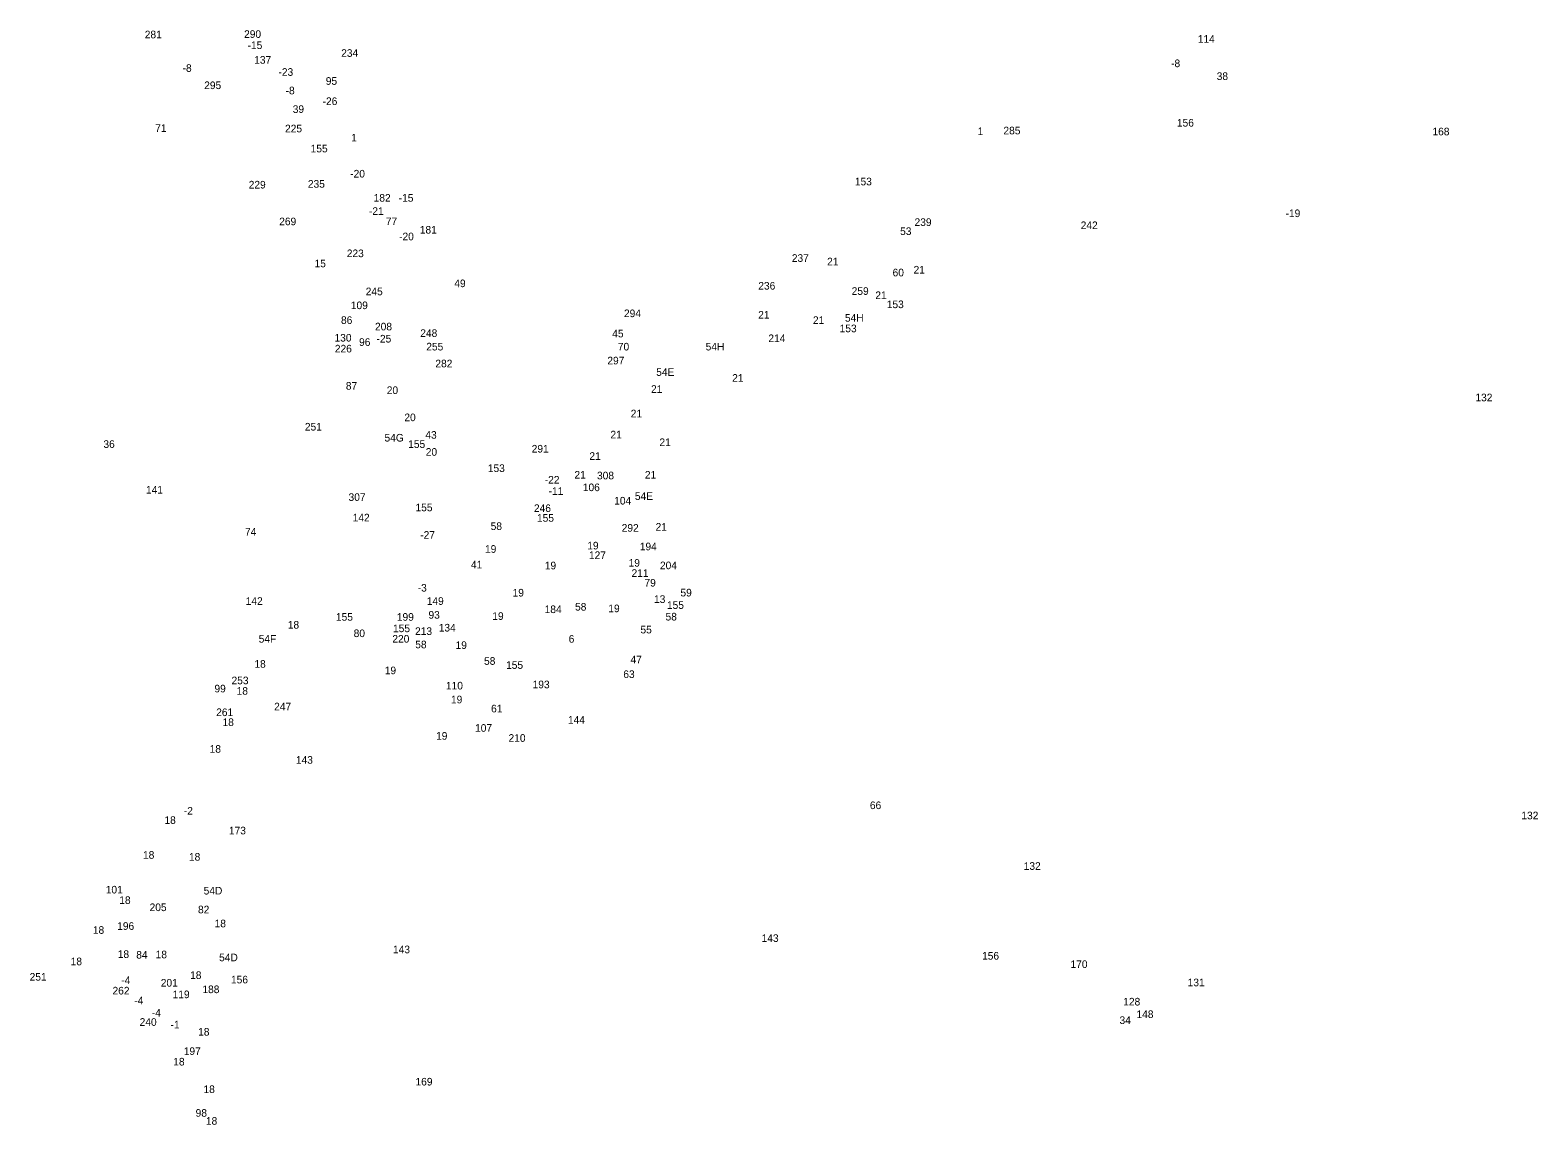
# Model space of a CAD drawing. Extents: x -784627 to -783624, y -969855 to -968411.
# Drawn here: x -784627 to -783638, y -969855 to -969137 of the extents above; entities that cross this region are included whole.
import ezdxf

# ---------------------------------------------------------------- set-up
doc = ezdxf.new("R2010")
doc.units = 0
doc.layers.add('Vrstva 15', color=7, linetype='Continuous')
doc.layers.add('Vrstva 24', color=7, linetype='Continuous')

msp = doc.modelspace()

# ---------------------------------------------------------------- texts
at = {"layer": 'Vrstva 15'}
for s, p in [('-15', (-784484.077, -969149.12)), ('-8', (-784526.71, -969164.1)), ('137', (-784479.74, -969158.75)), ('-23', (-784463.81, -969166.69)), ('-8', (-783878.23, -969160.99)), ('95', (-784432.774, -969172.57)), ('38', (-783848.323, -969169.42)), ('-8', (-784459.13, -969178.86)), ('-26', (-784434.862, -969185.85)), ('39', (-784454.465, -969191.04)), ('71', (-784544.67, -969203.48)), ('1', (-784005.14, -969205.6)), ('156', (-783874.422, -969200.01)), ('155', (-784442.7, -969216.92)), ('1', (-784416.09, -969209.79)), ('-20', (-784416.75, -969233.43)), ('153', (-784085.68, -969238.57)), ('182', (-784401.37, -969249.26)), ('-15', (-784384.947, -969249.3)), ('-21', (-784404.457, -969257.95)), ('77', (-784393.362, -969264.67)), ('-19', (-783803.139, -969259.4)), ('-20', (-784384.68, -969274.61)), ('181', (-784371.098, -969270.22)), ('53', (-784055.993, -969271.16)), ('15', (-784440.14, -969292.35)), ('21', (-784103.9, -969291.09)), ('49', (-784348.463, -969305.39)), ('60', (-784060.935, -969298.28)), ('109', (-784416.332, -969319.8)), ('153', (-784064.77, -969319.14)), ('86', (-784422.795, -969329.51)), ('153', (-784095.68, -969334.95)), ('54H', (-784092.201, -969328.03)), ('130', (-784427.04, -969341.08)), ('96', (-784410.946, -969343.92)), ('-25', (-784399.47, -969341.71)), ('45', (-784244.851, -969338.33)), ('70', (-784241.162, -969346.93)), ('54H', (-784183.571, -969346.92)), ('54E', (-784216.003, -969363.58)), ('  87', (-784423.342, -969372.67)), ('20', (-784392.774, -969375.5)), ('21', (-784219.42, -969374.74)), ('21', (-784166.18, -969367.46)), ('20', (-784381.214, -969393.33)), ('21', (-784232.73, -969390.82)), ('43', (-784367.461, -969404.84)), ('21', (-784246.04, -969404.64)), ('36', (-784578.665, -969410.86)), ('54G', (-784394.239, -969406.7)), ('155', (-784378.72, -969410.87)), ('21', (-784213.9, -969409.66)), ('20', (-784367.184, -969416.02)), ('21', (-784259.85, -969418.71)), ('153', (-784326.49, -969426.68)), ('-22', (-784289.11, -969434.28)), ('21', (-784269.65, -969431.02)), ('21', (-784223.44, -969431.02)), ('-11', (-784286.594, -969441.69)), ('106', (-784264.142, -969439.25)), ('155', (-784373.91, -969452.45)), ('104', (-784243.568, -969448.02)), ('54E', (-784230.023, -969445)), ('58', (-784324.613, -969464.72)), ('155', (-784294.23, -969459.32)), ('74', (-784485.77, -969468.4)), ('-27', (-784370.81, -969470.49)), ('21', (-784216.41, -969465.19)), ('19', (-784328.322, -969479.69)), ('127', (-784260.13, -969483.79)), ('41', (-784337.548, -969489.97)), ('79', (-784223.704, -969501.88)), ('-3', (-784372.45, -969505.17)), ('149', (-784366.55, -969513.86)), ('13', (-784217.44, -969512.6)), ('59', (-784200.105, -969508.34)), ('93', (-784365.414, -969522.93)), ('58', (-784269.253, -969517.62)), ('58', (-784209.883, -969524.12)), ('155', (-784208.97, -969516.53)), ('155', (-784426.12, -969524.26)), ('155', (-784388.68, -969531.79)), ('213', (-784374.22, -969533.62)), ('134', (-784358.678, -969531.36)), ('55', (-784226.333, -969532.61)), ('54F', (-784476.793, -969538.65)), ('80', (-784414.484, -969535.02)), ('58', (-784374.083, -969542.37)), ('19', (-784347.632, -969542.81)), ('6', (-784273.425, -969538.71)), ('58', (-784328.953, -969553.2)), ('47', (-784232.85, -969552.23)), ('19', (-784394.092, -969559.39)), ('155', (-784314.5, -969555.87)), ('63', (-784237.594, -969561.86)), ('99', (-784505.826, -969571.31)), ('110', (-784353.968, -969569.39)), ('19', (-784350.642, -969578.49)), ('61', (-784324.352, -969584.44)), ('19', (-784360.432, -969602.36)), ('107', (-784334.85, -969597.15)), ('-2', (-784525.89, -969651.51)), ('66', (-784075.826, -969647.9)), ('18', (-784538.61, -969657.63)), ('18', (-784552.67, -969680.49)), ('18', (-784522.54, -969681.75)), ('101', (-784577.128, -969703.27)), ('18', (-784568.24, -969710.14)), ('54D', (-784512.891, -969703.93)), ('82', (-784516.603, -969716.32)), ('18', (-784585.57, -969729.73)), ('18', (-784505.71, -969725.47)), ('18', (-784600.14, -969750.34)), ('84', (-784557.122, -969746)), ('18', (-784544.39, -969745.81)), ('54D', (-784502.761, -969747.74)), ('156', (-784002.242, -969746.68)), ('-4', (-784566.938, -969762.68)), ('156', (-784494.962, -969762.26)), ('-4', (-784558.398, -969776)), ('119', (-784533.25, -969771.98)), ('128', (-783909.63, -969776.78)), ('-4', (-784546.878, -969784.04)), ('34', (-783912.052, -969788.92)), ('148', (-783900.938, -969785.02)), ('-1', (-784534.607, -969791.82)), ('18', (-784516.51, -969796.56)), ('18', (-784532.83, -969816.15)), ('18', (-784512.99, -969834.24)), ('98', (-784518.164, -969849.78)), ('18', (-784511.42, -969855.04))]:
    msp.add_text(s, height=5, dxfattribs=at).set_placement(p)
at = {"layer": 'Vrstva 24'}
for s, p in [('281', (-784551.53, -969142.07)), ('290', (-784486.365, -969141.79)), ('114', (-783860.746, -969145)), ('234', (-784422.672, -969154.23)), ('295', (-784512.534, -969175.4)), ('225', (-784459.513, -969203.78)), ('285', (-783988.223, -969205.1)), ('168', (-783706.772, -969205.74)), ('229', (-784483.345, -969240.64)), ('235', (-784444.533, -969240.13)), ('269', (-784463.316, -969264.75)), ('239', (-784046.525, -969265.22)), ('242', (-783937.551, -969267.29)), ('223', (-784418.993, -969285.69)), ('237', (-784127.032, -969288.76)), ('21', (-784047.16, -969296.45)), ('245', (-784406.571, -969310.68)), ('236', (-784149.045, -969306.97)), ('259', (-784087.785, -969310.44)), ('21', (-784072.26, -969313.19)), ('294', (-784237.163, -969325.06)), ('21', (-784149.11, -969326.01)), ('208', (-784400.483, -969333.75)), ('21', (-784113.19, -969329.52)), ('248', (-784370.781, -969338.04)), ('214', (-784142.428, -969341.43)), ('226', (-784426.825, -969348.23)), ('255', (-784366.853, -969346.92)), ('282', (-784360.883, -969358.01)), ('297', (-784248.064, -969356.06)), ('132', (-783678.6, -969380.26)), ('251', (-784446.48, -969399.47)), ('291', (-784297.692, -969413.92)), ('308', (-784254.853, -969431.5)), ('141', (-784550.736, -969440.86)), ('307', (-784417.842, -969445.65)), ('246', (-784296.223, -969452.92)), ('142', (-784415.138, -969459.11)), ('292', (-784238.654, -969465.86)), ('19', (-784261.232, -969477.49)), ('194', (-784226.79, -969478.06)), ('19', (-784289.112, -969490.56)), ('19', (-784234.112, -969488.8)), ('204', (-784213.551, -969490.48)), ('211', (-784232.178, -969495.5)), ('142', (-784485.328, -969513.87)), ('19', (-784310.212, -969508.39)), ('19', (-784323.522, -969523.72)), ('184', (-784289.208, -969519.27)), ('19', (-784247.422, -969518.69)), ('18', (-784457.7, -969529.46)), ('199', (-784386.164, -969524.3)), ('220', (-784389.104, -969538.64)), ('18', (-784479.6, -969555.13)), ('253', (-784494.603, -969565.97)), ('18', (-784491.27, -969572.84)), ('193', (-784297.082, -969568.61)), ('247', (-784466.65, -969583.13)), ('261', (-784504.682, -969586.85)), ('144', (-784273.916, -969591.83)), ('18', (-784500.51, -969593.37)), ('18', (-784508.98, -969610.91)), ('210', (-784312.89, -969603.73)), ('143', (-784452.388, -969618.12)), ('132', (-783648.46, -969654.6)), ('173', (-784496.31, -969664.48)), ('132', (-783974.93, -969687.76)), ('205', (-784548.363, -969714.83)), ('196', (-784569.614, -969727.15)), ('143', (-784146.858, -969735.06)), ('18', (-784569.25, -969745.56)), ('143', (-784388.688, -969742.48)), ('251', (-784627.05, -969760.48)), ('18', (-784521.78, -969759.38)), ('170', (-783944.22, -969752.16)), ('262', (-784572.684, -969769.55)), ('201', (-784541.02, -969764.4)), ('188', (-784513.71, -969768.67)), ('131', (-783867.368, -969764.14)), ('240', (-784554.891, -969790.13)), ('197', (-784525.962, -969809.27)), ('169', (-784373.914, -969829.28))]:
    msp.add_text(s, height=5, dxfattribs=at).set_placement(p)

doc.saveas('drawing.dxf')
